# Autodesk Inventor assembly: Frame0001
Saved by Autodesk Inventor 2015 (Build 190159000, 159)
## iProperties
Created: 2020-03
Part Number: Frame0001
Document SubType Name: Assembly
Designer: 徐冠倫
Mass: 12110.5 g
Surface Area: 10291.1 cm^2
Volume: 1542.74 cm^3
Density: 7.85 g/cm^3
_FrameDoc: Frame Assembly
_Version: 15.0.0
Author: 徐冠倫
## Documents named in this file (4)
- C:\Users\徐冠倫\Desktop\Topic 13-4_簡支樑的剪力及彎曲力矩\Topic 13-4_簡支樑的剪力及彎曲力矩\Frame\Frame0001.iam
- C:\Users\徐冠倫\Desktop\Topic 13-4_簡支樑的剪力及彎曲力矩\Topic 13-4_簡支樑的剪力及彎曲力矩\Frame\Skeleton0001.ipt
- C:\Users\徐冠倫\Desktop\Topic 13-4_簡支樑的剪力及彎曲力矩\Topic 13-4_簡支樑的剪力及彎曲力矩\Frame\ISO 30x30x3 00000001.ipt
- ISO 30x30x3 00000001.ipt
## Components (2 placed, 2 different names)
1. Frame Reference Model
2. ISO 30x30x3 00000001:1
